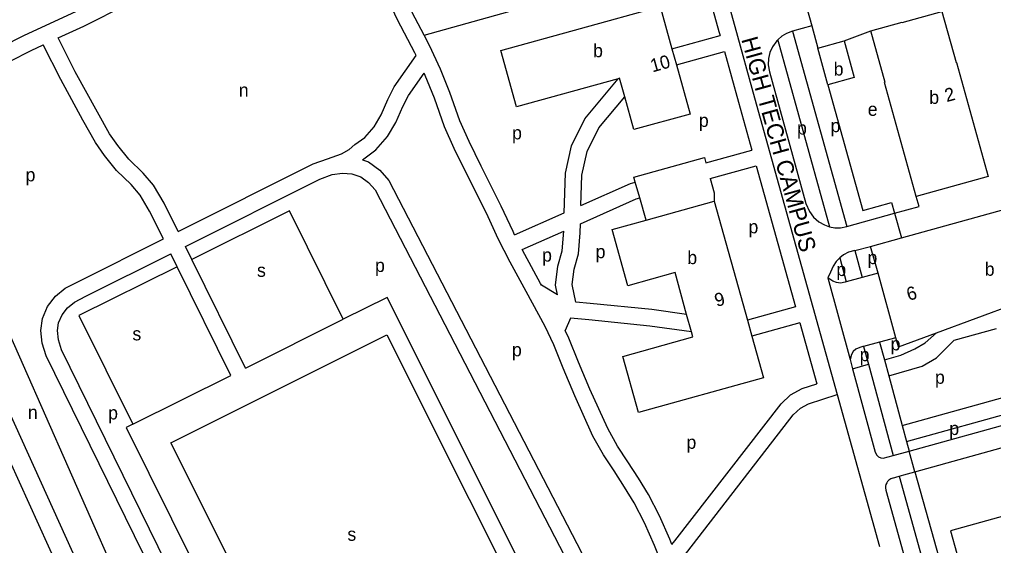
# Model space of a CAD drawing. Extents: x 158358 to 160383, y 379531 to 380764.
# Drawn here: x 159216.2 to 159510.8, y 380061.3 to 380220.5 of the extents above; entities that cross this region are included whole.
import ezdxf

# ---------------------------------------------------------------- set-up
doc = ezdxf.new("R2010")
doc.units = 0
for name, color, linetype in [('BLT_Basislijn', 7, 'Continuous'), ('BLT_Bebouwing', 7, 'Continuous'), ('BLT_Centroide', 7, 'Continuous'), ('BLT_Huisnummer', 7, 'Continuous'), ('BLT_Straatnaam', 7, 'Continuous'), ('BLT_Vlakafsluiter', 7, 'Continuous')]:
    doc.layers.add(name, color=color, linetype=linetype)

msp = doc.modelspace()

# ---------------------------------------------------------------- linework, layer by layer
at = {"layer": 'BLT_Basislijn'}
for p, q in [((159338.57, 380215.77), (159412.85, 380236.48)), ((159454.17, 380224.34), (159455.79, 380218.56)), ((159455.79, 380218.56), (159457.67, 380211.84)), ((159465.64, 380214), (159473.62, 380217.06)), ((159413.52, 380211.55), (159428.06, 380215.59)), ((159414.86, 380206.73), (159429.4, 380210.77)), ((159468.83, 380150.59), (159473.59, 380151.8)), ((159450.88, 380133.57), (159436.32, 380129.51)), ((159210.62, 380131.18), (159259.52, 380020.21)), ((159382.84, 380130.12), (159381.27, 380126.41)), ((159452.22, 380128.75), (159437.66, 380124.69))]:
    msp.add_line(p, q, dxfattribs=at)
for points in [[(159400.14, 380316.14), (159427.71, 380216.83)], [(159404.97, 380317.41), (159432.49, 380218.33)], [(159181.03, 380197.05), (159188.24, 380200.64), (159195.23, 380203.52), (159202.18, 380207.01), (159210.97, 380212.28), (159217.58, 380215.63), (159233.46, 380222.94), (159246.59, 380229.57), (159263.22, 380238.61), (159271.15, 380242.3), (159279.19, 380247.09), (159282.74, 380250.27), (159286.8, 380253.31), (159291.21, 380255.55), (159297.33, 380257.54), (159310.66, 380260.6)], [(159338.57, 380215.77), (159334.99, 380222.62), (159330.02, 380233.28), (159324.7, 380244.91), (159321.31, 380251.68)], [(159227.93, 380214.89), (159235.64, 380218.44), (159248.91, 380225.14), (159265.47, 380234.14), (159273.49, 380237.87), (159281.07, 380242.39)], [(159336.14, 380209.54), (159335.77, 380210.34), (159330.5, 380220.4), (159326.47, 380229.05)], [(159427.71, 380216.83), (159428.06, 380215.59)], [(159432.49, 380218.33), (159438.48, 380196.75), (159463.46, 380107.02)], [(159449.94, 380216.94), (159448.12, 380216.23), (159446.74, 380215.39)], [(159455.79, 380218.56), (159449.94, 380216.94)], [(159449.94, 380216.94), (159466.37, 380157.84)], [(159264.22, 380156.32), (159260, 380164.88), (159256.79, 380170.31), (159253.6, 380173.94), (159249.31, 380178.18), (159245.97, 380182.34), (159243.44, 380185.91), (159239.81, 380192.47), (159233.11, 380204.61), (159227.93, 380214.89)], [(159365.96, 380155.33), (159365.46, 380156.32), (159361.9, 380164.03), (159355.87, 380176.08), (159352.2, 380183.6), (159349.37, 380189.82), (159346.38, 380198.4), (159343.52, 380205.48), (159340.25, 380212.55), (159338.57, 380215.77)], [(159445.5, 380214.25), (159445.26, 380214.02), (159443.92, 380212.22), (159443.16, 380210.51), (159442.72, 380208.68), (159442.64, 380206.71), (159442.99, 380204.62)], [(159446.74, 380215.39), (159445.67, 380214.4), (159445.5, 380214.25)], [(159445.5, 380214.25), (159461.2, 380157.78)], [(159183.08, 380192.48), (159190.31, 380196.08), (159197.3, 380198.97), (159204.59, 380202.62), (159213.39, 380207.9), (159219.76, 380211.13), (159223.39, 380212.8)], [(159259.74, 380154.08), (159255.59, 380162.5), (159252.72, 380167.37), (159249.97, 380170.51), (159245.59, 380174.82), (159241.97, 380179.33), (159239.2, 380183.25), (159235.43, 380190.05), (159228.69, 380202.27), (159223.39, 380212.8)], [(159429.4, 380210.77), (159433.66, 380195.41), (159437.68, 380180.98)], [(159309.34, 380178.34), (159313.59, 380179.88), (159315.91, 380181.19), (159317.66, 380182.61), (159320.62, 380184.8), (159323.43, 380188), (159325.58, 380191.61), (159327.6, 380196.29), (159329.56, 380200.08), (159336.14, 380209.54)], [(159246.18, 380011.53), (159249.72, 380020.35), (159242.08, 380037.85), (159212.76, 380102.49), (159171.52, 380192.1), (159165.17, 380205.1)], [(159319.93, 380178.01), (159320.73, 380178.66), (159324.03, 380181.09), (159327.49, 380185.05), (159330.04, 380189.33), (159332.12, 380194.14), (159333.85, 380197.5), (159338.57, 380204.27)], [(159409.9, 380057.28), (159408.24, 380061.34), (159405.21, 380068.18), (159402.09, 380074.3), (159399.21, 380079.03), (159396.05, 380083.92), (159392.79, 380088.8), (159389.65, 380094.46), (159384.11, 380106.67), (159380.62, 380114.96), (159377.78, 380122.09), (159375.17, 380127.61), (159369.42, 380138.21), (159364.61, 380147.03), (159360.96, 380154.13), (159357.4, 380161.87), (159351.39, 380173.87), (159347.68, 380181.46), (159344.72, 380187.95), (159341.7, 380196.64), (159338.93, 380203.49), (159338.57, 380204.27)], [(159442.99, 380204.62), (159454.04, 380164.84)], [(159380.96, 380161.99), (159381.29, 380174.02), (159383.1, 380182.24), (159387.18, 380190.41), (159397.26, 380202.56)], [(159460.68, 380200.73), (159471.27, 380162.64), (159479.94, 380165.07), (159480.84, 380161.86)], [(159386.02, 380164.23), (159386.27, 380173.41), (159387.85, 380180.56), (159391.39, 380187.66), (159399.24, 380197.11)], [(159423.77, 380177.15), (159437.68, 380180.98)], [(159264.22, 380156.32), (159305.06, 380176.77), (159309.34, 380178.34)], [(159319.93, 380178.01), (159321.73, 380177.36), (159325.18, 380174.93), (159327.91, 380171.76), (159396.43, 380039.34)], [(159402.45, 380171.28), (159402.02, 380172.82), (159423.33, 380178.72), (159423.77, 380177.15)], [(159425.12, 380172.34), (159439.02, 380176.16)], [(159439.02, 380176.16), (159450.88, 380133.57)], [(159266.43, 380151.83), (159307.04, 380172.17), (159310.81, 380173.55), (159313.93, 380174.01), (159316.77, 380173.82), (159319.41, 380172.88), (159321.79, 380171.2), (159323.74, 380168.94), (159393.11, 380034.87)], [(159425.12, 380172.34), (159426.33, 380168.02), (159426.33, 380165.48)], [(159386.02, 380164.23), (159401.04, 380170.89), (159402.45, 380171.28)], [(159403.81, 380166.47), (159402.45, 380171.28)], [(159385.87, 380158.69), (159402.73, 380166.17), (159403.81, 380166.47)], [(159405.71, 380159.74), (159403.81, 380166.47)], [(159480.84, 380161.86), (159488.25, 380163.92), (159487.41, 380166.94)], [(159454.04, 380164.84), (159455.07, 380162.43), (159456.37, 380160.69), (159457.98, 380159.28), (159459.66, 380158.33), (159461.2, 380157.78)], [(159314.14, 380129.8), (159297.88, 380162.55), (159268.36, 380147.91)], [(159365.96, 380155.33), (159380.96, 380161.99)], [(159466.37, 380157.84), (159480.84, 380161.86)], [(159480.84, 380161.86), (159482.93, 380154.39)], [(159384.5, 380134.98), (159383.39, 380140.31), (159383.92, 380144.91), (159385.27, 380149.62), (159385.79, 380155.92), (159385.87, 380158.69)], [(159461.2, 380157.78), (159462.81, 380157.49), (159464.45, 380157.44), (159466.37, 380157.84)], [(159424.15, 379962.9), (159422.07, 379961.1), (159419.42, 379959.39), (159339.93, 379920.21), (159336.41, 379918.87), (159332.9, 379918.38), (159329.52, 379918.6), (159326.34, 379919.46), (159322.82, 379921.64), (159319.91, 379924.62), (159317.59, 379928.49), (159224.33, 380118.68), (159223.12, 380122.52), (159222.7, 380126.41), (159223.18, 380129.99), (159224.73, 380133.69), (159227.11, 380136.76), (159230.07, 380139.21), (159234.05, 380141.22), (159259.74, 380154.08)], [(159368.25, 380150.88), (159380.82, 380156.45)], [(159378.95, 380137.14), (159378.33, 380140.08), (159378.99, 380145.89), (159380.32, 380150.53), (159380.82, 380156.45)], [(159268.36, 380147.91), (159266.43, 380151.83)], [(159321.98, 379930.88), (159228.98, 380120.55), (159228.04, 380123.55), (159227.73, 380126.34), (159228.05, 380128.66), (159229.09, 380131.15), (159230.72, 380133.26), (159232.82, 380134.99), (159236.29, 380136.75), (159261.95, 380149.6)], [(159263.88, 380145.69), (159261.95, 380149.6)], [(159374.05, 380140.15), (159373.81, 380140.6), (159369.03, 380149.37), (159368.25, 380150.88)], [(159464.26, 380148.33), (159463.22, 380147.22), (159462.27, 380145.82), (159461.49, 380144.01), (159460.71, 380142.29)], [(159468.83, 380150.59), (159466.94, 380150.07), (159465.42, 380149.25), (159464.26, 380148.33)], [(159464.26, 380148.33), (159466.22, 380141.07)], [(159468.83, 380150.59), (159471.05, 380142.38)], [(159263.88, 380145.69), (159234.15, 380130.95), (159250.47, 380098.02)], [(159280.09, 380112.8), (159263.88, 380145.69)], [(159284.56, 380115.03), (159268.36, 380147.91)], [(159466.22, 380141.07), (159465.88, 380140.98), (159464.45, 380140.73), (159463.28, 380140.87), (159462.19, 380141.35), (159460.71, 380142.29)], [(159460.71, 380142.29), (159467.38, 380117.63)], [(159471.05, 380142.38), (159466.22, 380141.07)], [(159475.85, 380143.69), (159471.05, 380142.38)], [(159378.95, 380137.14), (159374.05, 380140.15)], [(159381.2, 380028.82), (159327.43, 380136.39), (159314.14, 380129.8)], [(159417.96, 380131.26), (159407.41, 380132.71), (159388.84, 380134.55), (159384.5, 380134.98)], [(159284.56, 380115.03), (159314.14, 380129.8)], [(159419.41, 380126.02), (159406.82, 380127.74), (159388.35, 380129.57), (159382.84, 380130.12)], [(159452.22, 380128.75), (159457.35, 380110.3)], [(159413.5, 380061.69), (159412.84, 380063.3), (159409.72, 380070.33), (159406.46, 380076.74), (159403.45, 380081.69), (159400.22, 380086.67), (159397.06, 380091.41), (159394.12, 380096.7), (159388.69, 380108.68), (159385.25, 380116.86), (159382.37, 380124.09), (159381.27, 380126.41)], [(159477.77, 380117.5), (159482.73, 380118.95), (159487.01, 380120.84), (159490.13, 380122.63), (159493.53, 380125.73)], [(159479.08, 380112.67), (159489.18, 380115.63), (159493.51, 380118.12), (159498.87, 380123.44), (159511.64, 380126.98)], [(159476.32, 380122.87), (159471.49, 380121.57)], [(159481.27, 380124.2), (159476.32, 380122.87)], [(159476.32, 380122.87), (159477.77, 380117.5)], [(159471.49, 380121.57), (159471.29, 380121.52), (159470.32, 380121.22), (159469.17, 380120.71), (159468.37, 380120.02), (159467.77, 380119.14), (159467.38, 380117.63)], [(159471.49, 380121.57), (159472.96, 380116.17)], [(159467.38, 380117.63), (159468.14, 380114.83)], [(159468.14, 380114.83), (159472.96, 380116.17)], [(159472.96, 380116.17), (159480.41, 380088.58)], [(159477.77, 380117.5), (159479.08, 380112.67)], [(159250.47, 380098.02), (159280.09, 380112.8)], [(159468.14, 380114.83), (159474.95, 380089.62), (159475.44, 380088.64), (159475.98, 380088.15), (159476.64, 380087.83), (159477.42, 380087.78), (159480.41, 380088.58)], [(159202.17, 380111.15), (159207.31, 380100), (159236.59, 380035.42), (159243.21, 380020.25), (159241.51, 380016), (159185.59, 379978.81), (159141.72, 379949.29)], [(159413.5, 380061.69), (159414.38, 380062.76), (159446.5, 380104.21), (159449.41, 380106.97), (159452.88, 380108.85), (159457.35, 380110.3)], [(159479.08, 380112.67), (159483.15, 380097.61)], [(159415.39, 380056.09), (159418.29, 380059.65), (159450.22, 380100.85), (159452.38, 380102.89), (159454.86, 380104.24), (159463.46, 380107.02)], [(159463.46, 380107.02), (159476.27, 380061.01)], [(159483.15, 380097.61), (159517.25, 380107.09)], [(159484.49, 380092.79), (159518.6, 380102.28)], [(159487, 380083.63), (159558.75, 380103.58)], [(159485.3, 380089.9), (159519.42, 380099.39)], [(159250.47, 380098.02), (159248.49, 380097.03), (159310.29, 379972.49), (159335.31, 379984.69)], [(159483.15, 380097.61), (159484.49, 380092.79)], [(159484.49, 380092.79), (159485.3, 380089.9)], [(159480.41, 380088.58), (159485.3, 380089.9)], [(159483.63, 380082.7), (159487, 380083.63)], [(159487, 380083.63), (159494.29, 380057.47)], [(159480.25, 380081.76), (159479.66, 380081.5), (159479.13, 380081.14), (159478.7, 380080.71), (159478.45, 380080.34), (159478.18, 380079.79), (159478.09, 380079.28), (159478.05, 380078.78), (159478.17, 380078.06), (159500, 379999.75), (159502.26, 379991.38), (159503.81, 379983.58), (159504.71, 379976.78), (159505.3, 379969.31), (159506.3, 379944.33)], [(159480.25, 380081.76), (159482.18, 380082.29)], [(159482.18, 380082.29), (159483.63, 380082.7)], [(159482.18, 380082.29), (159504.82, 380001.07), (159507.13, 379992.52), (159508.75, 379984.4), (159509.68, 379977.31), (159510.29, 379969.61)]]:
    msp.add_lwpolyline(points, dxfattribs=at)
msp.add_lwpolyline([(159327.32, 380125.11), (159377.14, 380025.65), (159311.79, 379992.91), (159261.97, 380092.37)], close=True, dxfattribs=at)
at = {"layer": 'BLT_Bebouwing'}
for p, q in [((159493.53, 380125.73), (159517.88, 380134.74)), ((159482.03, 380121.48), (159493.53, 380125.73)), ((159482.03, 380121.48), (159481.27, 380124.2))]:
    msp.add_line(p, q, dxfattribs=at)
for points in [[(159397.26, 380202.56), (159366.48, 380194), (159361.74, 380211.05), (159409.96, 380224.38), (159413.52, 380211.55)], [(159473.62, 380217.06), (159483.1, 380219.69), (159483.14, 380219.57), (159495.17, 380222.91), (159499.48, 380207.41), (159499.61, 380207.45)], [(159487.41, 380166.94), (159477.83, 380201.41), (159477.96, 380201.44), (159473.62, 380217.06)], [(159457.67, 380211.84), (159465.64, 380214)], [(159465.64, 380214), (159468.65, 380202.89), (159460.68, 380200.73)], [(159413.52, 380211.55), (159414.86, 380206.73)], [(159460.68, 380200.73), (159457.67, 380211.84)], [(159499.61, 380207.45), (159509.17, 380173), (159487.41, 380166.94)], [(159414.86, 380206.73), (159418.99, 380191.85), (159402.02, 380187.14), (159399.24, 380197.11)], [(159399.24, 380197.11), (159397.7, 380202.68), (159397.26, 380202.56)], [(159482.93, 380154.39), (159542.98, 380171.08)], [(159405.71, 380159.74), (159426.33, 380165.48)], [(159426.33, 380165.48), (159436.32, 380129.51)], [(159417.96, 380131.26), (159414.45, 380143.9), (159400.2, 380139.93), (159395.48, 380156.9), (159405.71, 380159.74)], [(159473.59, 380151.8), (159482.93, 380154.39)], [(159475.85, 380143.69), (159473.59, 380151.8)], [(159481.27, 380124.2), (159475.85, 380143.69)], [(159419.41, 380126.02), (159417.96, 380131.26)], [(159436.32, 380129.51), (159437.66, 380124.69)], [(159437.66, 380124.69), (159441.17, 380112.08), (159403.39, 380101.59), (159398.66, 380118.57), (159419.85, 380124.45), (159419.41, 380126.02)], [(159553.96, 380081.41), (159497.74, 380065.78), (159499.64, 380058.95)]]:
    msp.add_lwpolyline(points, dxfattribs=at)
at = {"layer": 'BLT_Vlakafsluiter'}
msp.add_line((159487, 380083.63), (159485.3, 380089.9), dxfattribs=at)

# ---------------------------------------------------------------- texts
at = {"layer": 'BLT_Centroide'}
for s, p in [('b', (159389.68, 380209.06)), ('b', (159462.43, 380203.51)), ('n', (159282.54, 380197.11)), ('b', (159491.33, 380194.94)), ('e', (159472.73, 380191.32)), ('p', (159421.66, 380187.97)), ('p', (159461.49, 380186.38)), ('p', (159365.18, 380184.21)), ('p', (159451.35, 380185.64)), ('p', (159218.07, 380171.5)), ('p', (159436.66, 380155.78)), ('p', (159390.44, 380148.26)), ('p', (159374.26, 380147.23)), ('b', (159418.17, 380146.47)), ('p', (159472.64, 380146.47)), ('s', (159288.05, 380142.62)), ('p', (159323.74, 380144.09)), ('p', (159463.23, 380142.87)), ('b', (159508.11, 380142.95)), ('s', (159250.38, 380123.4)), ('p', (159365.14, 380118.58)), ('p', (159479.65, 380120.38)), ('p', (159470.29, 380117.1)), ('p', (159493.06, 380110.27)), ('n', (159218.77, 380099.63)), ('p', (159243.04, 380099.49)), ('p', (159497.39, 380094.78)), ('p', (159417.91, 380090.6)), ('s', (159315.38, 380062.78))]:
    msp.add_text(s, height=4, dxfattribs=at).set_placement(p)
at = {"layer": 'BLT_Huisnummer'}
for s, rotation, p in [('10', 15.5338, (159407.61, 380204.44)), ('2', 15.5167, (159496.61, 380195.46)), ('6', 15.5208, (159485.09, 380135.34)), ('9', 15.5338, (159427.03, 380133.49))]:
    msp.add_text(s, height=4, rotation=rotation, dxfattribs=at).set_placement(p)
at = {"layer": 'BLT_Straatnaam'}
msp.add_text('HIGH TECH CAMPUS', height=5, rotation=285.5194, dxfattribs=at).set_placement((159434.45, 380214.49))

doc.saveas('drawing.dxf')
